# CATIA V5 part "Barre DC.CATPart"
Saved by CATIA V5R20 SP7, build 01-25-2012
Part number: Barre DC
Bounding box of the stored display mesh (mm): x -2 to 2, y 57.014 to 75.652, z -2.991 to 21.419
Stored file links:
  U:\IAO_bon\Barre DC.CATPart
  U:\IAO_bon\Barre AB.CATPart
  U:\IAO_bon\Cqueguiner_IAo.CATProduct
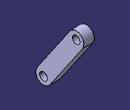
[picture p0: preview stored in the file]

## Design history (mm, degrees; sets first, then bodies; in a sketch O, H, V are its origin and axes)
Set1
  Point1 "Point C": linked copy from another document
  Point2 "Point D": linked copy from another document
Body1 (main body)
  Sketch1 on yz-plane, origin (0, 0, 0), H (0, 1, 0), V (0, 0, 1)
    line L1 (57.5276, 1.6993) -> (70.1931, 20.1271)
    arc A1 centre (72.6655, 18.4278) radius 3 from (70.1931, 20.1271) to (75.1378, 16.7286) cw
    point P3 (72.6655, 18.4278)
    line L2 (75.1378, 16.7286) -> (62.4724, -1.6993)
    arc A2 centre (60, 0) radius 3 from (62.4724, -1.6993) to (57.5276, 1.6993) cw
    point P6 (60, 0)
    reference projected point E1 (72.6655, 18.4278) from Point1
    reference projected point E2 (60, 0) from Point2
    circle A3 centre (72.6655, 18.4278) radius 1.5
    circle A4 centre (60, 0) radius 1.5
    radius A1 = 3
    distance L2 L1 = 6
    radius A3 = 1.5
    radius A4 = 1.5
    tangency: A1 L1, A2 L1, A2 L2
    coincidence: P3 E1, P6 E2
  Pad1: profile Sketch1, direction (1, 0, 0), length 2, opposite side length 2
